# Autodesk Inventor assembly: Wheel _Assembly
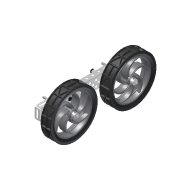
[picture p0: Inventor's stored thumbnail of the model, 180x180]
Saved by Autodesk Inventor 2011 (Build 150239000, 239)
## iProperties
Created: 2007-12
Part Number: Wheel _Assembly
Document SubType Name: Assembly
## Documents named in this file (12)
- C:\Data Folder\VEX 2011\Inventor Datasets\Unit 16\Components\Wheel _Assembly.iam
- C:\Data Folder\VEX 2011\Inventor Datasets\Unit 16\Components\SCREW-832-0250.ipt
- C:\Data Folder\VEX 2011\Inventor Datasets\Unit 16\Components\BEARING-FLAT.ipt
- C:\Data Folder\VEX 2011\Inventor Datasets\Unit 16\Components\SHAFT-3000.ipt
- C:\Data Folder\VEX 2011\Inventor Datasets\Unit 16\Components\VEX-MEDIUM-WHEEL.iam
- C:\Data Folder\VEX 2011\Inventor Datasets\Unit 16\Components\BEARING-RIVET.ipt
- C:\Data Folder\VEX 2011\Inventor Datasets\Unit 16\Components\VL-RAIL-21-16 RevA.ipt
- C:\Data Folder\VEX 2011\Inventor Datasets\Unit 16\Components\BEAM-1000.ipt
- C:\Data Folder\VEX 2011\Inventor Datasets\Unit 16\Components\Shaft_Collar.iam
- C:\Data Folder\VEX 2011\Inventor Datasets\Unit 16\Components\VEX-MEDIUM-WHEEL_MIR5.iam
- C:\Data Folder\VEX 2011\Inventor Datasets\Unit 16\Components\SHAFT-3000_MIR4.ipt
- C:\Data Folder\VEX 2011\Inventor Datasets\Unit 16\Components\Shaft_Collar_MIR2.iam
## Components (20 placed, 11 different names)
1. VL-RAIL-21-16 RevA:1 — Mate:10, Mate:68, Mate:69, Mate:71, Mate:73, Mate:74, Flush:12, Mate:75, Flush:13, Angle:10, Angle:11, Mate:80, Mate:81, Mate:82, Mate:98, Flush:17, Mate:99, Flush:18, Angle:16, Angle:17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
2. VEX-MEDIUM-WHEEL:2 [sub-assembly] — Angle:15, Mate:102, Mate:108, Mate:111
3. SHAFT-3000:3 — Angle:15, Mate:102, Mate:103, Mate:107, Angle:17, Mate:109, Flush:20
4. SCREW-832-0250:23 — Mate:24, Mate:117
5. BEAM-1000:4 — Mate:24, Mate:26, Mate:68, Mate:69, Mate:70, Mate:117
6. SCREW-832-0250:28 — Mate:26, Mate:70, Mate:71
7. BEARING-RIVET:23 — Mate:75, Flush:13, Angle:11
8. BEARING-RIVET:24 — Mate:11, Flush:12, Angle:10
9. BEARING-RIVET:28 — Mate:99, Flush:18
10. BEARING-RIVET:29 — Mate:98, Flush:17
11. BEARING-FLAT:16 — Mate:80, Mate:81, Mate:82, Mate:116
12. BEARING-FLAT:18 — Mate:10, Mate:11, Mate:73, Mate:74, Mate:103, Mate:110
13. Shaft_Collar:1 [sub-assembly] — Mate:107, Mate:108, Angle:16, Flush:19
14. Shaft_Collar:2 [sub-assembly] — Mate:109, Mate:110, Angle:18, Flush:21
15. VEX-MEDIUM-WHEEL_MIR5:1 [sub-assembly] — Mate:112, Angle:19, Mate:113
16. SHAFT-3000_MIR4:1 — Mate:112, Angle:19, Mate:114, Mate:115, Mate:116, Flush:20, Angle:20
17. Shaft_Collar_MIR2:1 [sub-assembly] — Mate:113, Mate:114, Flush:19, Angle:22
18. Shaft_Collar_MIR2:2 [sub-assembly] — Mate:115, Flush:21, Angle:21
19. SCREW-832-0250:29 — Mate:120, Mate:121
20. BEAM-1000:5 — Mate:118, Mate:119, Mate:120, Mate:121
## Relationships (50: Mate 33, Angle 10, Flush 7)
- Mate:10: VL-RAIL-21-16 RevA:1 ↔ BEARING-FLAT:18
- Mate:11: BEARING-RIVET:24 ↔ BEARING-FLAT:18
- Mate:24: SCREW-832-0250:23 ↔ BEAM-1000:4
- Mate:26: BEAM-1000:4 ↔ SCREW-832-0250:28
- Mate:68: VL-RAIL-21-16 RevA:1 ↔ BEAM-1000:4
- Mate:69: VL-RAIL-21-16 RevA:1 ↔ BEAM-1000:4
- Mate:70: BEAM-1000:4 ↔ SCREW-832-0250:28
- Mate:71: VL-RAIL-21-16 RevA:1 ↔ SCREW-832-0250:28
- Mate:73: VL-RAIL-21-16 RevA:1 ↔ BEARING-FLAT:18
- Mate:74: VL-RAIL-21-16 RevA:1 ↔ BEARING-FLAT:18
- Flush:12: VL-RAIL-21-16 RevA:1 ↔ BEARING-RIVET:24
- Mate:75: VL-RAIL-21-16 RevA:1 ↔ BEARING-RIVET:23
- Flush:13: VL-RAIL-21-16 RevA:1 ↔ BEARING-RIVET:23
- Angle:10: VL-RAIL-21-16 RevA:1 ↔ BEARING-RIVET:24
- Angle:11: VL-RAIL-21-16 RevA:1 ↔ BEARING-RIVET:23
- Mate:80: VL-RAIL-21-16 RevA:1 ↔ BEARING-FLAT:16
- Mate:81: VL-RAIL-21-16 RevA:1 ↔ BEARING-FLAT:16
- Mate:82: VL-RAIL-21-16 RevA:1 ↔ BEARING-FLAT:16
- Angle:15: VEX-MEDIUM-WHEEL:2 ↔ SHAFT-3000:3
- Mate:98: VL-RAIL-21-16 RevA:1 ↔ BEARING-RIVET:29
- Flush:17: VL-RAIL-21-16 RevA:1 ↔ BEARING-RIVET:29
- Mate:99: VL-RAIL-21-16 RevA:1 ↔ BEARING-RIVET:28
- Flush:18: VL-RAIL-21-16 RevA:1 ↔ BEARING-RIVET:28
- Mate:102: VEX-MEDIUM-WHEEL:2 ↔ SHAFT-3000:3
- Mate:103: SHAFT-3000:3 ↔ BEARING-FLAT:18
- Mate:107: SHAFT-3000:3 ↔ Shaft_Collar:1
- Mate:108: VEX-MEDIUM-WHEEL:2 ↔ Shaft_Collar:1
- Angle:16: VL-RAIL-21-16 RevA:1 ↔ Shaft_Collar:1
- Angle:17: VL-RAIL-21-16 RevA:1 ↔ SHAFT-3000:3
- Mate:109: SHAFT-3000:3 ↔ Shaft_Collar:2
- Mate:110: BEARING-FLAT:18 ↔ Shaft_Collar:2
- Angle:18: VL-RAIL-21-16 RevA:1 ↔ Shaft_Collar:2
- Mate:111: VL-RAIL-21-16 RevA:1 ↔ VEX-MEDIUM-WHEEL:2
- Mate:112: VEX-MEDIUM-WHEEL_MIR5:1 ↔ SHAFT-3000_MIR4:1
- Angle:19: VEX-MEDIUM-WHEEL_MIR5:1 ↔ SHAFT-3000_MIR4:1
- Mate:113: VEX-MEDIUM-WHEEL_MIR5:1 ↔ Shaft_Collar_MIR2:1
- Mate:114: SHAFT-3000_MIR4:1 ↔ Shaft_Collar_MIR2:1
- Mate:115: SHAFT-3000_MIR4:1 ↔ Shaft_Collar_MIR2:2
- Mate:116: BEARING-FLAT:16 ↔ SHAFT-3000_MIR4:1
- Flush:19: Shaft_Collar:1 ↔ Shaft_Collar_MIR2:1
- Flush:20: SHAFT-3000:3 ↔ SHAFT-3000_MIR4:1
- Flush:21: Shaft_Collar:2 ↔ Shaft_Collar_MIR2:2
- Angle:20: VL-RAIL-21-16 RevA:1 ↔ SHAFT-3000_MIR4:1
- Angle:21: VL-RAIL-21-16 RevA:1 ↔ Shaft_Collar_MIR2:2
- Angle:22: VL-RAIL-21-16 RevA:1 ↔ Shaft_Collar_MIR2:1
- Mate:117: SCREW-832-0250:23 ↔ BEAM-1000:4
- Mate:118: VL-RAIL-21-16 RevA:1 ↔ BEAM-1000:5
- Mate:119: VL-RAIL-21-16 RevA:1 ↔ BEAM-1000:5
- Mate:120: SCREW-832-0250:29 ↔ BEAM-1000:5
- Mate:121: SCREW-832-0250:29 ↔ BEAM-1000:5
